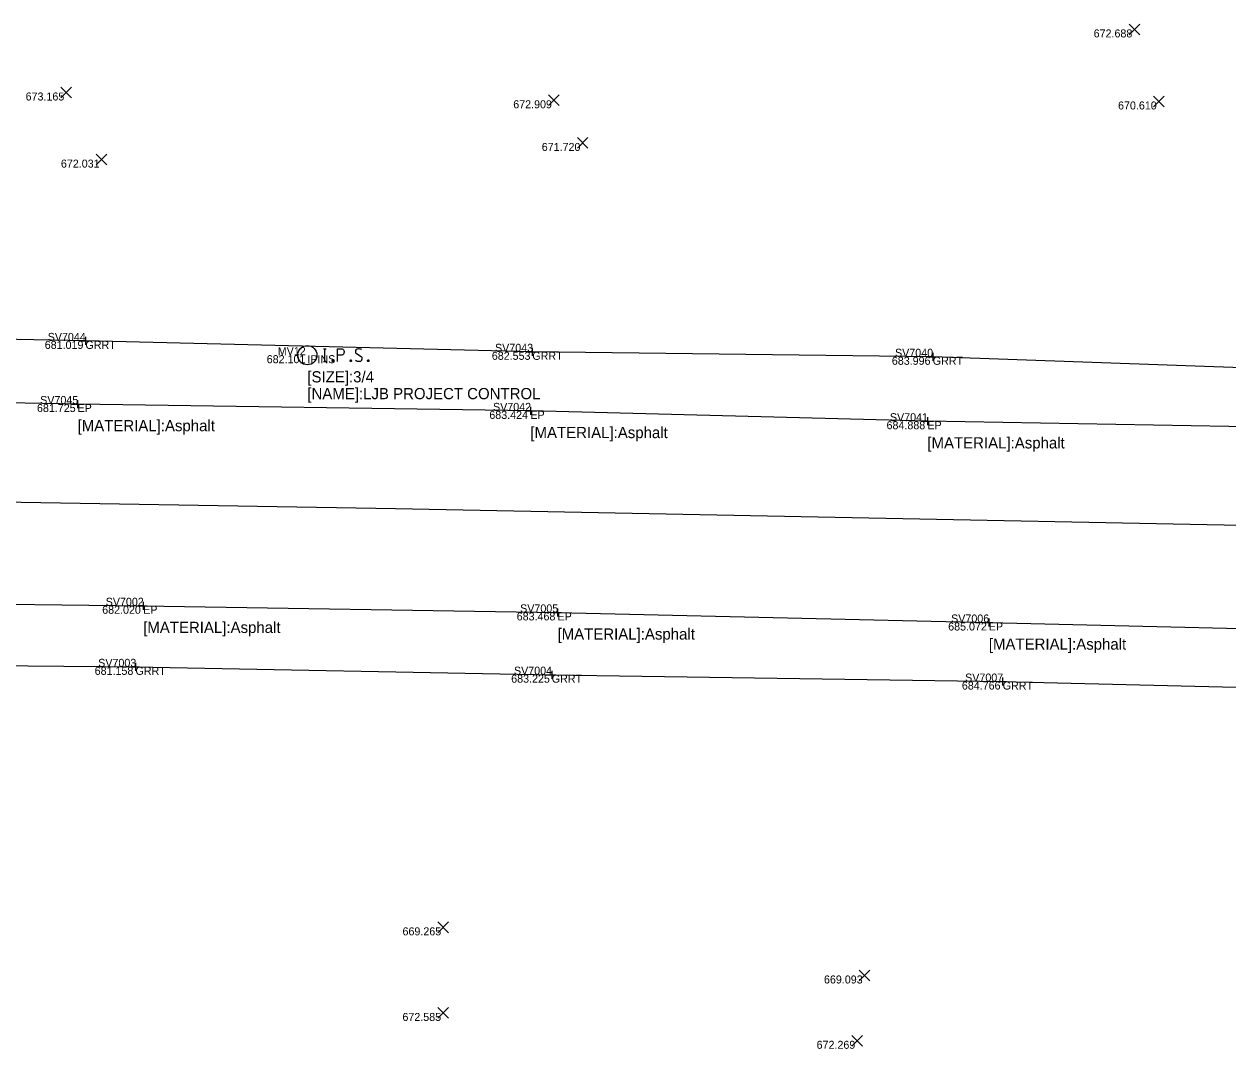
# Model space of a CAD drawing. Extents: x 1659932 to 1663108, y 619867 to 620611.
# Drawn here: x 1660636.8 to 1660787.2, y 620178.1 to 620306.1 of the extents above; entities that cross this region are included whole.
import ezdxf

# ---------------------------------------------------------------- set-up
doc = ezdxf.new("R2010")
doc.units = 0
for name, color, linetype in [('PM_X_CL_Dashed', 7, 'Continuous'), ('PV_X_EOP', 7, 'Continuous'), ('RD_X_GR_Rt', 7, 'Continuous'), ('RS_Raster1', 7, 'Continuous'), ('SV_P_Mon_Cells_Set_Text', 7, 'Continuous'), ('SV_X_Random_Point', 7, 'Continuous'), ('SV_X_Shot_Marker', 7, 'Continuous'), ('SV_X_Text', 7, 'Continuous'), ('SV_X_Text_Comment', 7, 'Continuous'), ('SV_X_Text_Elevation', 7, 'Continuous'), ('SV_X_Text_Name', 7, 'Continuous')]:
    doc.layers.add(name, color=color, linetype=linetype)

msp = doc.modelspace()

# ---------------------------------------------------------------- linework, layer by layer
at = {"layer": 'PM_X_CL_Dashed'}
msp.add_lwpolyline([(1660473.33, 620249.8), (1660569.82, 620247.52), (1660683.17, 620245.58), (1660845.9, 620242.37), (1660966.03, 620239.29), (1661085.35, 620237.14), (1661180.4, 620235.01), (1661204.65, 620234.52)], dxfattribs=at)
at = {"layer": 'PV_X_EOP'}
for points in [[(1661208.92, 620246.9), (1661156.94, 620248.21), (1661087.29, 620250.6), (1661037.39, 620250.48), (1660981.01, 620252.16), (1660916.41, 620253.34), (1660855.2, 620254.44), (1660801.44, 620255.57), (1660749.64, 620256.49), (1660700.03, 620257.78), (1660643.44, 620258.64), (1660593.17, 620259.57)], [(1660597.37, 620234.1), (1660651.64, 620233.44), (1660703.42, 620232.61), (1660757.32, 620231.35), (1660809.76, 620230.12), (1660857.03, 620229.26), (1660910.07, 620228.44), (1660968.25, 620227.38), (1661028.27, 620226.15), (1661081.58, 620225.11), (1661140.41, 620223.53), (1661201.71, 620222.7)]]:
    msp.add_lwpolyline(points, dxfattribs=at)
at = {"layer": 'RD_X_GR_Rt'}
for points in [[(1661224.69, 620250.79), (1661156.18, 620253.35), (1661087.54, 620257.19), (1661037.26, 620258.5), (1660981.37, 620259.47), (1660918.68, 620260.81), (1660856.77, 620262.08), (1660800.7, 620262.74), (1660750.31, 620264.54), (1660700.27, 620265.16), (1660644.43, 620266.52), (1660592.86, 620267.53)], [(1660596.86, 620226.32), (1660650.68, 620225.81), (1660702.7, 620224.83), (1660759.05, 620223.97), (1660808.86, 620222.78), (1660856.77, 620221.69), (1660908.98, 620220.55), (1660971.26, 620219.59), (1661027.54, 620217.92), (1661083.51, 620217.29), (1661139.61, 620218.11), (1661215.13, 620218.24)]]:
    msp.add_lwpolyline(points, dxfattribs=at)
at = {"layer": 'RS_Raster1'}
for points in [[(1660674.18, 620265.54), (1660674.53, 620265.54)], [(1660674.35, 620263.94), (1660674.35, 620265.54)], [(1660675.92, 620263.94), (1660675.92, 620265.54), (1660676.45, 620265.54), (1660676.5, 620265.53), (1660676.58, 620265.5), (1660676.61, 620265.48), (1660676.65, 620265.45), (1660676.69, 620265.39), (1660676.72, 620265.32), (1660676.75, 620265.22), (1660676.75, 620265.07), (1660676.73, 620265.02), (1660676.71, 620264.95), (1660676.67, 620264.86), (1660676.62, 620264.82), (1660676.59, 620264.8), (1660676.54, 620264.77), (1660676.45, 620264.76), (1660675.92, 620264.76)], [(1660678.93, 620265.43), (1660678.91, 620265.45), (1660678.87, 620265.48), (1660678.77, 620265.51), (1660678.65, 620265.54), (1660678.56, 620265.54), (1660678.53, 620265.54), (1660678.39, 620265.5), (1660678.27, 620265.43), (1660678.19, 620265.32), (1660678.17, 620265.22), (1660678.17, 620265.15), (1660678.19, 620265.05), (1660678.28, 620264.96), (1660678.88, 620264.58), (1660678.94, 620264.53), (1660678.96, 620264.48), (1660678.98, 620264.4), (1660678.98, 620264.33), (1660678.97, 620264.25), (1660678.96, 620264.2), (1660678.94, 620264.14), (1660678.92, 620264.09), (1660678.89, 620264.05), (1660678.86, 620264.01), (1660678.83, 620263.99), (1660678.78, 620263.96), (1660678.75, 620263.95), (1660678.65, 620263.94), (1660678.5, 620263.94), (1660678.4, 620263.96), (1660678.26, 620264.05), (1660678.17, 620264.13)], [(1660674.18, 620263.94), (1660674.53, 620263.94)], [(1660675.31, 620264.15), (1660675.37, 620264.15), (1660675.4, 620264.13), (1660675.43, 620264.08), (1660675.43, 620264.01), (1660675.4, 620263.96), (1660675.37, 620263.94), (1660675.31, 620263.94), (1660675.28, 620263.96), (1660675.25, 620264.01), (1660675.25, 620264.08), (1660675.28, 620264.13), (1660675.31, 620264.15)], [(1660677.56, 620264.15), (1660677.62, 620264.15), (1660677.65, 620264.13), (1660677.68, 620264.08), (1660677.68, 620264.01), (1660677.65, 620263.96), (1660677.62, 620263.94), (1660677.56, 620263.94), (1660677.53, 620263.96), (1660677.49, 620264.01), (1660677.49, 620264.08), (1660677.53, 620264.13), (1660677.56, 620264.15)], [(1660679.74, 620264.15), (1660679.8, 620264.15), (1660679.83, 620264.13), (1660679.86, 620264.08), (1660679.86, 620264.01), (1660679.83, 620263.96), (1660679.8, 620263.94), (1660679.74, 620263.94), (1660679.71, 620263.96), (1660679.68, 620264.01), (1660679.68, 620264.08), (1660679.71, 620264.13), (1660679.74, 620264.15)]]:
    msp.add_lwpolyline(points, dxfattribs=at)
msp.add_circle((1660672.16, 620264.74), 1.2, dxfattribs=at)
at = {"layer": 'SV_X_Random_Point'}
for p, q in [((1660774.86, 620304.76), (1660776.19, 620306.1)), ((1660774.86, 620306.1), (1660776.19, 620304.76)), ((1660641.35, 620296.88), (1660642.68, 620298.22)), ((1660641.35, 620298.22), (1660642.68, 620296.88)), ((1660702.31, 620295.92), (1660703.64, 620297.25)), ((1660702.31, 620297.25), (1660703.64, 620295.92)), ((1660777.92, 620295.76), (1660779.25, 620297.1)), ((1660777.92, 620297.1), (1660779.25, 620295.76)), ((1660705.9, 620290.58), (1660707.23, 620291.92)), ((1660705.9, 620291.92), (1660707.23, 620290.58)), ((1660645.77, 620288.5), (1660647.11, 620289.84)), ((1660645.77, 620289.84), (1660647.11, 620288.5)), ((1660688.45, 620192.6), (1660689.78, 620193.94)), ((1660688.45, 620193.94), (1660689.78, 620192.6)), ((1660741.12, 620186.59), (1660742.45, 620187.93)), ((1660741.12, 620187.93), (1660742.45, 620186.59)), ((1660688.45, 620181.91), (1660689.78, 620183.25)), ((1660688.45, 620183.25), (1660689.78, 620181.91)), ((1660740.22, 620178.43), (1660741.55, 620179.77)), ((1660740.22, 620179.77), (1660741.55, 620178.43))]:
    msp.add_line(p, q, dxfattribs=at)
at = {"layer": 'SV_X_Shot_Marker'}
for p, q in [((1660643.93, 620266.52), (1660644.93, 620266.52)), ((1660644.43, 620267.02), (1660644.43, 620266.02)), ((1660644.43, 620266.52), (1660644.43, 620266.52)), ((1660699.77, 620265.16), (1660700.77, 620265.16)), ((1660700.27, 620265.66), (1660700.27, 620264.66)), ((1660700.27, 620265.16), (1660700.27, 620265.16)), ((1660750.31, 620265.04), (1660750.31, 620264.04)), ((1660749.81, 620264.54), (1660750.81, 620264.54)), ((1660750.31, 620264.54), (1660750.31, 620264.54)), ((1660642.94, 620258.64), (1660643.94, 620258.64)), ((1660643.44, 620259.14), (1660643.44, 620258.14)), ((1660643.44, 620258.64), (1660643.44, 620258.64)), ((1660699.53, 620257.78), (1660700.53, 620257.78)), ((1660700.03, 620258.28), (1660700.03, 620257.28)), ((1660700.03, 620257.78), (1660700.03, 620257.78)), ((1660749.14, 620256.49), (1660750.14, 620256.49)), ((1660749.64, 620256.99), (1660749.64, 620255.99)), ((1660749.64, 620256.49), (1660749.64, 620256.49)), ((1660651.14, 620233.44), (1660652.14, 620233.44)), ((1660651.64, 620233.94), (1660651.64, 620232.94)), ((1660651.64, 620233.44), (1660651.64, 620233.44)), ((1660703.42, 620233.11), (1660703.42, 620232.11)), ((1660702.92, 620232.61), (1660703.92, 620232.61)), ((1660703.42, 620232.61), (1660703.42, 620232.61)), ((1660757.32, 620231.85), (1660757.32, 620230.85)), ((1660756.82, 620231.35), (1660757.82, 620231.35)), ((1660757.32, 620231.35), (1660757.32, 620231.35)), ((1660650.18, 620225.81), (1660651.18, 620225.81)), ((1660650.68, 620226.31), (1660650.68, 620225.31)), ((1660650.68, 620225.81), (1660650.68, 620225.81)), ((1660702.2, 620224.83), (1660703.2, 620224.83)), ((1660702.7, 620225.33), (1660702.7, 620224.33)), ((1660702.7, 620224.83), (1660702.7, 620224.83)), ((1660759.05, 620224.47), (1660759.05, 620223.47)), ((1660758.55, 620223.97), (1660759.55, 620223.97)), ((1660759.05, 620223.97), (1660759.05, 620223.97))]:
    msp.add_line(p, q, dxfattribs=at)

# ---------------------------------------------------------------- texts
at = {"layer": 'SV_P_Mon_Cells_Set_Text'}
for s, p in [('[SIZE]:3/4', (1660672.16, 620261.34)), ('[NAME]:LJB PROJECT CONTROL', (1660672.16, 620259.24))]:
    msp.add_text(s, height=1.4, dxfattribs=at).set_placement(p)
at = {"layer": 'SV_X_Text'}
for p in [(1660643.44, 620255.24), (1660700.03, 620254.38), (1660749.64, 620253.09), (1660651.64, 620230.04), (1660703.42, 620229.21), (1660757.32, 620227.95)]:
    msp.add_text('[MATERIAL]:Asphalt', height=1.4, dxfattribs=at).set_placement(p)
at = {"layer": 'SV_X_Text_Comment'}
for s, p in [('GRRT', (1660644.43, 620265.52)), ('IPINS', (1660672.16, 620263.74)), ('GRRT', (1660700.27, 620264.16)), ('GRRT', (1660750.31, 620263.54)), ('EP', (1660643.44, 620257.64)), ('EP', (1660700.03, 620256.78)), ('EP', (1660749.64, 620255.49)), ('EP', (1660651.64, 620232.44)), ('EP', (1660703.42, 620231.61)), ('EP', (1660757.32, 620230.35)), ('GRRT', (1660650.68, 620224.81)), ('GRRT', (1660702.7, 620223.83)), ('GRRT', (1660759.05, 620222.97))]:
    msp.add_text(s, height=1, dxfattribs=at).set_placement(p)
at = {"layer": 'SV_X_Text_Elevation'}
for s, p in [('672.688', (1660770.42, 620304.43)), ('673.165', (1660636.95, 620296.55)), ('672.909', (1660697.89, 620295.58)), ('670.610', (1660773.47, 620295.43)), ('671.720', (1660701.45, 620290.25)), ('672.031', (1660641.36, 620288.17)), ('681.019', (1660639.34, 620265.52)), ('682.101', (1660667.08, 620263.74)), ('682.553', (1660695.21, 620264.16)), ('683.996', (1660745.2, 620263.54)), ('681.725', (1660638.37, 620257.64)), ('683.424', (1660694.9, 620256.78)), ('684.888', (1660744.54, 620255.49)), ('682.020', (1660646.52, 620232.44)), ('683.468', (1660698.32, 620231.61)), ('685.072', (1660752.24, 620230.35)), ('681.158', (1660645.58, 620224.81)), ('683.225', (1660697.63, 620223.83)), ('684.766', (1660753.95, 620222.97)), ('669.265', (1660684.05, 620192.27)), ('669.093', (1660736.72, 620186.26)), ('672.585', (1660684.04, 620181.58)), ('672.269', (1660735.8, 620178.1))]:
    msp.add_text(s, height=1, dxfattribs=at).set_placement(p)
at = {"layer": 'SV_X_Text_Name'}
for s, p in [('SV7044', (1660639.71, 620266.52)), ('SV7043', (1660695.61, 620265.16)), ('MV12', (1660668.46, 620264.74)), ('SV7040', (1660745.6, 620264.54)), ('SV7045', (1660638.77, 620258.64)), ('SV7042', (1660695.36, 620257.78)), ('SV7041', (1660744.96, 620256.49)), ('SV7002', (1660646.96, 620233.44)), ('SV7005', (1660698.75, 620232.61)), ('SV7006', (1660752.61, 620231.35)), ('SV7003', (1660646.02, 620225.81)), ('SV7004', (1660697.98, 620224.83)), ('SV7007', (1660754.36, 620223.97))]:
    msp.add_text(s, height=1, dxfattribs=at).set_placement(p)

doc.saveas('drawing.dxf')
